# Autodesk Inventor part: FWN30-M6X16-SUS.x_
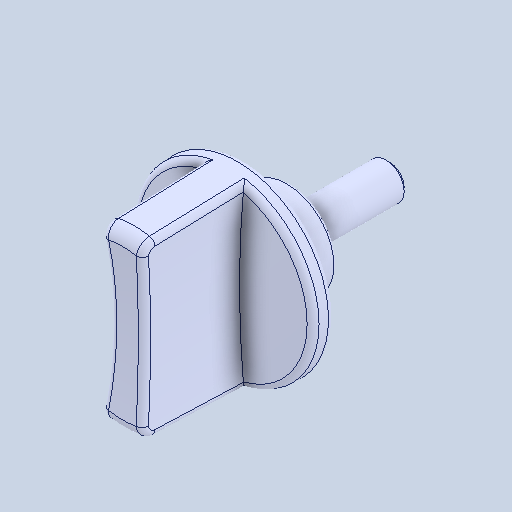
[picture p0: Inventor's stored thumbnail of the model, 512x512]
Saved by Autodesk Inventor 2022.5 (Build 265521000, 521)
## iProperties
Created: 2024-05
Part Number: FWN30-M6X16-SUS.x_
Material: 一般
Document SubType Name: Modeling
Designer: ImaoCorp
Density: 1 g/cm^3
Appearance: 既定
Author: ImaoCorp
Sending System: SOLIDWORKS 2022-2022290
MC: AMD64
MC_MODEL: Intel64 Family 6 Model 60 Stepping 3, GenuineIntel
OS: Windows_NT
FRU: Parasolid Version 33.1, build 260,  4-25-2022
FORMAT: text
GUISE: transmit
KEY: FILEFWN30-M6X16-SUS.x_t
DATE: Mon May 20 16:40:40 2024
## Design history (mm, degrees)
feature "Base1"
node "ソリッド1"
